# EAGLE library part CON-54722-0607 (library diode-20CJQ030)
Molex 54722-0607 low profile board to board connector with 60pins and a pitch 0.5mm
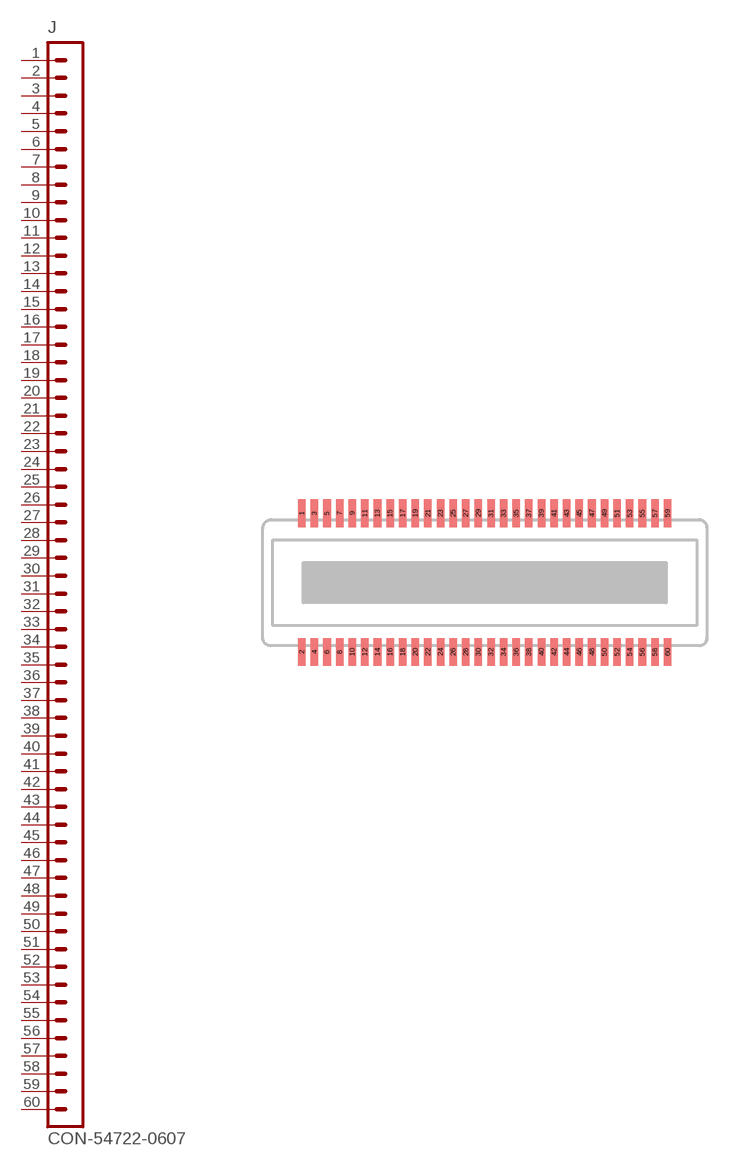
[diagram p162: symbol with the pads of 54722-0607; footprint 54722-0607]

Designator prefix J

## CON-54722-0607"  [54722-0607]
1  1  pas
2  2  pas
3  3  pas
4  4  pas
5  5  pas
6  6  pas
7  7  pas
8  8  pas
9  9  pas
10  10  pas
11  11  pas
12  12  pas
13  13  pas
14  14  pas
15  15  pas
16  16  pas
17  17  pas
18  18  pas
19  19  pas
20  20  pas
21  21  pas
22  22  pas
23  23  pas
24  24  pas
25  25  pas
26  26  pas
27  27  pas
28  28  pas
29  29  pas
30  30  pas
31  31  pas
32  32  pas
33  33  pas
34  34  pas
35  35  pas
36  36  pas
37  37  pas
38  38  pas
39  39  pas
40  40  pas
41  41  pas
42  42  pas
43  43  pas
44  44  pas
45  45  pas
46  46  pas
47  47  pas
48  48  pas
49  49  pas
50  50  pas
51  51  pas
52  52  pas
53  53  pas
54  54  pas
55  55  pas
56  56  pas
57  57  pas
58  58  pas
59  59  pas
60  60  pas

## Footprint 54722-0607 (pad centres in mm)
Molex 54722-0607 Bord to Board connector 60pin.
smd 0.3 x 1.1: 1 -7.25,2.75; 2 -7.25,-2.75; 3 -6.75,2.75; 4 -6.75,-2.75; 5 -6.25,2.75; 6 -6.25,-2.75; 7 -5.75,2.75; 8 -5.75,-2.75; 9 -5.25,2.75; 10 -5.25,-2.75; 11 -4.75,2.75; 12 -4.75,-2.75; 13 -4.25,2.75; 14 -4.25,-2.75; 15 -3.75,2.75; 16 -3.75,-2.75; 17 -3.25,2.75; 18 -3.25,-2.75; 19 -2.75,2.75; 20 -2.75,-2.75; 21 -2.25,2.75; 22 -2.25,-2.75; 23 -1.75,2.75; 24 -1.75,-2.75; 25 -1.25,2.75; 26 -1.25,-2.75; 27 -0.75,2.75; 28 -0.75,-2.75; 29 -0.25,2.75; 30 -0.25,-2.75; 31 0.25,2.75; 32 0.25,-2.75; 33 0.75,2.75; 34 0.75,-2.75; 35 1.25,2.75; 36 1.25,-2.75; 37 1.75,2.75; 38 1.75,-2.75; 39 2.25,2.75; 40 2.25,-2.75; 41 2.75,2.75; 42 2.75,-2.75; 43 3.25,2.75; 44 3.25,-2.75; 45 3.75,2.75; 46 3.75,-2.75; 47 4.25,2.75; 48 4.25,-2.75; 49 4.75,2.75; 50 4.75,-2.75; 51 5.25,2.75; 52 5.25,-2.75; 53 5.75,2.75; 54 5.75,-2.75; 55 6.25,2.75; 56 6.25,-2.75; 57 6.75,2.75; 58 6.75,-2.75; 59 7.25,2.75; 60 7.25,-2.75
